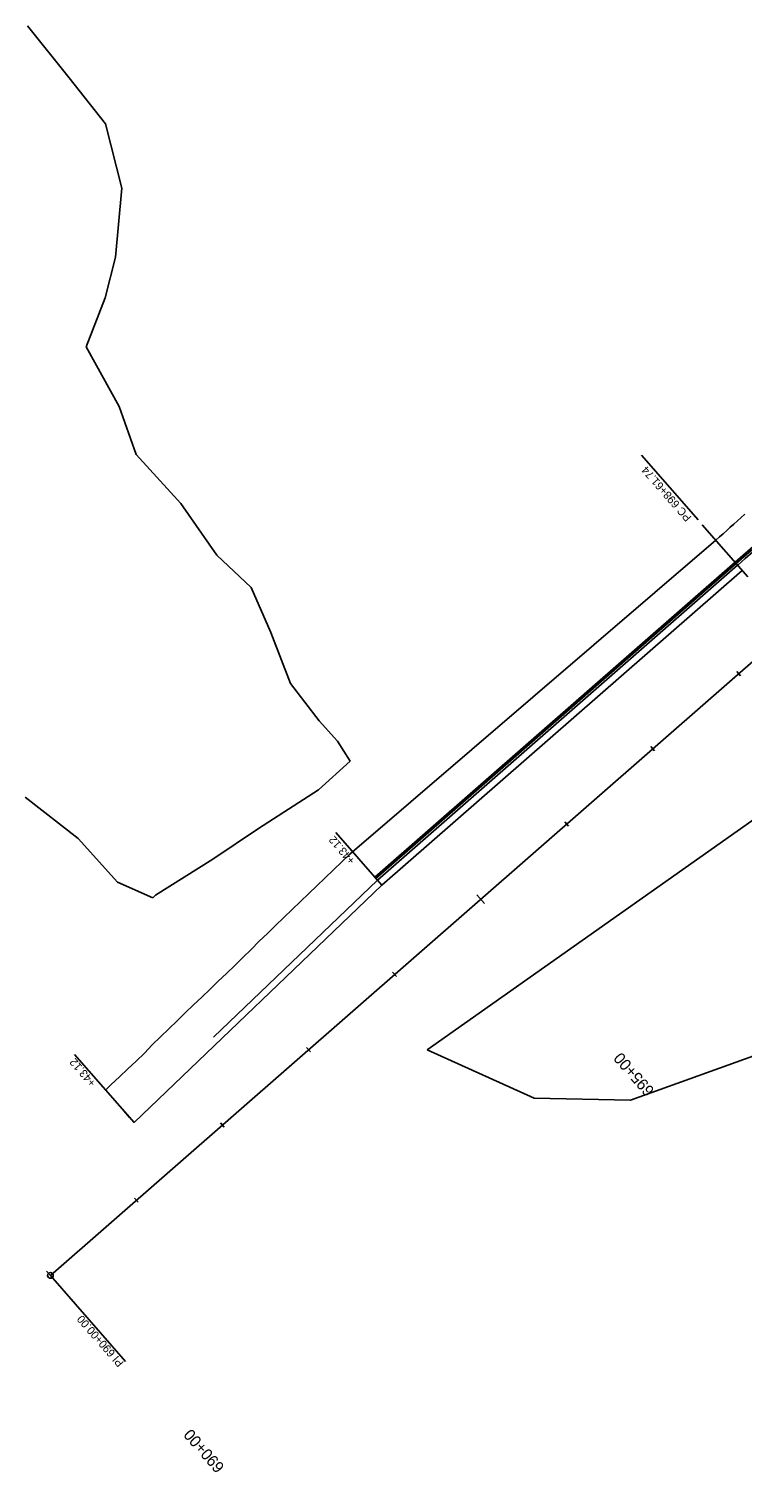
# Model space of a CAD drawing. Extents: x 1300404 to 1323571, y 237813 to 252077.
# Drawn here: x 1308409 to 1309033, y 238765 to 240028 of the extents above; entities that cross this region are included whole.
import ezdxf

# ---------------------------------------------------------------- set-up
doc = ezdxf.new("R2010")
doc.units = 0
for name, color, linetype in [('R_Barrier Wall', 7, 'Continuous'), ('R_Const Limits', 7, 'Continuous'), ('R_Flooplain', 7, 'Continuous'), ('R_Horz Alg Annot', 7, 'Continuous'), ('R_Horz Alg Annot Leader', 7, 'Continuous'), ('R_Horz Alg Major Ticks', 7, 'Continuous'), ('R_Horz Alg Minor Ticks', 7, 'Continuous'), ('R_Horz Alg Station Annot', 7, 'Continuous'), ('R_Lane Edge', 7, 'Continuous'), ('R_Proposed', 7, 'Continuous'), ('R_Shoulder', 7, 'Continuous'), ('R_Sidewalk Edge', 7, 'Continuous')]:
    doc.layers.add(name, color=color, linetype=linetype)

msp = doc.modelspace()

# ---------------------------------------------------------------- linework, layer by layer
at = {"layer": 'R_Barrier Wall'}
for p, q in [((1308711.5, 239285.2), (1309026.7, 239560.9)), ((1308712.3, 239284.2), (1309027.6, 239559.9)), ((1308711.5, 239285.2), (1308712.3, 239284.2))]:
    msp.add_line(p, q, dxfattribs=at)
for radius in [5712.7, 5714.1]:
    msp.add_arc((1305266.3, 243861.4), radius, 311.1667, 314.0235, dxfattribs=at)
at = {"layer": 'R_Const Limits'}
msp.add_line((1308689.6, 239305.6), (1309009.8, 239580.2), dxfattribs=at)
msp.add_lwpolyline([(1308500.8, 239070.6), (1308496.9, 239075.1), (1308490.3, 239082.6), (1308481.1, 239093.2), (1308475.8, 239099.1), (1308480.9, 239103.8), (1308488.2, 239110.7), (1308495.5, 239117.5), (1308502.8, 239124.3), (1308510, 239131.3), (1308516.8, 239138.7), (1308524, 239145.7), (1308531.2, 239152.7), (1308538.4, 239159.6), (1308545.6, 239166.6), (1308552.8, 239173.5), (1308560, 239180.4), (1308567.3, 239187.3), (1308574.5, 239194.3), (1308581.7, 239201.2), (1308588.9, 239208.2), (1308596, 239215.2), (1308603.2, 239222.2), (1308610.3, 239229.3), (1308617.5, 239236.2), (1308624.7, 239243.2), (1308631.9, 239250.1), (1308639.1, 239257.1), (1308646.4, 239264), (1308653.6, 239271), (1308660.8, 239277.9), (1308668, 239284.8), (1308675.3, 239291.7), (1308682.5, 239298.7), (1308689.6, 239305.6), (1308689.6, 239305.6)], dxfattribs=at)
msp.add_arc((1305232.5, 243831.7), 5687.1, 311.62, 311.9623, dxfattribs=at)
at = {"layer": 'R_Flooplain'}
for p, q in [((1308407.5, 240030.2), (1308444, 239984.8)), ((1308444, 239984.8), (1308475.9, 239944.5)), ((1308475.9, 239944.5), (1308490, 239888.2)), ((1308490, 239888.2), (1308484.6, 239827.9)), ((1308484.6, 239827.9), (1308475.5, 239792.1)), ((1308475.5, 239792.1), (1308458.9, 239749.4)), ((1308458.9, 239749.4), (1308487.7, 239697.1)), ((1308487.7, 239697.1), (1308502.6, 239655.2)), ((1308502.6, 239655.2), (1308541.6, 239612.2)), ((1308541.6, 239612.2), (1308573.2, 239567)), ((1308573.2, 239567), (1308603.2, 239538.9)), ((1308603.2, 239538.9), (1308620.6, 239499.3)), ((1308620.6, 239499.3), (1308637.8, 239454.9)), ((1308637.8, 239454.9), (1308662.7, 239422.2)), ((1308662.7, 239422.2), (1308678.8, 239404.4)), ((1308678.8, 239404.4), (1308690, 239386.9)), ((1308690, 239386.9), (1308662.2, 239361.7)), ((1308757.3, 239134.3), (1309093.3, 239371.4)), ((1308452, 239319.1), (1308405.4, 239355.3)), ((1308662.2, 239361.7), (1308609.7, 239328)), ((1308486.4, 239281), (1308452, 239319.1)), ((1308609.7, 239328), (1308569.6, 239301)), ((1308569.6, 239301), (1308519.7, 239269.7)), ((1308517.1, 239267.4), (1308486.4, 239281)), ((1308519.7, 239269.7), (1308517.1, 239267.4)), ((1308757.3, 239134.3), (1308850.8, 239092.1)), ((1308935.3, 239090.2), (1309053.6, 239132.7)), ((1308850.8, 239092.1), (1308935.3, 239090.2))]:
    msp.add_line(p, q, dxfattribs=at)
at = {"layer": 'R_Horz Alg Annot Leader'}
for p, q in [((1308717.7, 239278.3), (1308677.3, 239324.4)), ((1308500.8, 239070.6), (1308448.6, 239130.3))]:
    msp.add_line(p, q, dxfattribs=at)
for points in [[(1308994.3, 239598), (1308944.8, 239654.5)], [(1309037.8, 239548.2), (1308998, 239593.6)], [(1308427.6, 238936.9), (1308493.4, 238861.6)]]:
    msp.add_lwpolyline(points, dxfattribs=at)
at = {"layer": 'R_Horz Alg Major Ticks'}
for points in [[(1308800.7, 239269.8), (1308807.3, 239262.3)], [(1308424.3, 238940.7), (1308430.9, 238933.1)]]:
    msp.add_lwpolyline(points, dxfattribs=at)
at = {"layer": 'R_Horz Alg Minor Ticks'}
for points in [[(1309028.2, 239465.4), (1309031.5, 239461.6)], [(1308952.9, 239399.6), (1308956.2, 239395.8)], [(1308877.6, 239333.7), (1308880.9, 239330)], [(1308727, 239202.1), (1308730.3, 239198.3)], [(1308651.8, 239136.3), (1308655.1, 239132.5)], [(1308576.5, 239070.4), (1308579.8, 239066.7)], [(1308501.2, 239004.6), (1308504.5, 239000.9)]]:
    msp.add_lwpolyline(points, dxfattribs=at)
at = {"layer": 'R_Lane Edge'}
for p, q in [((1308717.7, 239278.3), (1309032.8, 239553.8)), ((1308500.8, 239070.6), (1308717.7, 239278.3))]:
    msp.add_line(p, q, dxfattribs=at)
at = {"layer": 'R_Proposed'}
msp.add_line((1308427.6, 238936.9), (1312793.8, 242754.8), dxfattribs=at)
msp.add_circle((1308427.6, 238936.9), 2.5, dxfattribs=at)
at = {"layer": 'R_Shoulder'}
for p, q in [((1308713.7, 239282.7), (1309028.9, 239558.4)), ((1308570.2, 239145.3), (1308713.7, 239282.7))]:
    msp.add_line(p, q, dxfattribs=at)
msp.add_arc((1305266.3, 243861.4), 5716.1, 311.1667, 314.0235, dxfattribs=at)
at = {"layer": 'R_Sidewalk Edge'}
msp.add_line((1308717.7, 239278.3), (1309032.8, 239553.8), dxfattribs=at)

# ---------------------------------------------------------------- texts
at = {"layer": 'R_Horz Alg Annot'}
for s, rotation, p in [('PC 698+61.74', 131.1667, (1308989, 239600.3)), ('+43.12', 130.5769, (1308694.7, 239300.2)), ('+43.12', 130.5769, (1308467.9, 239105.7)), ('PI 690+00.00', 131.1667, (1308492.3, 238860.6))]:
    msp.add_text(s, height=7, rotation=rotation, dxfattribs=at).set_placement(p)
at = {"layer": 'R_Horz Alg Station Annot'}
for s, p in [('695+00', (1308956.7, 239099)), ('690+00', (1308580.5, 238769.6))]:
    msp.add_text(s, height=10, rotation=131.1667, dxfattribs=at).set_placement(p)

doc.saveas('drawing.dxf')
